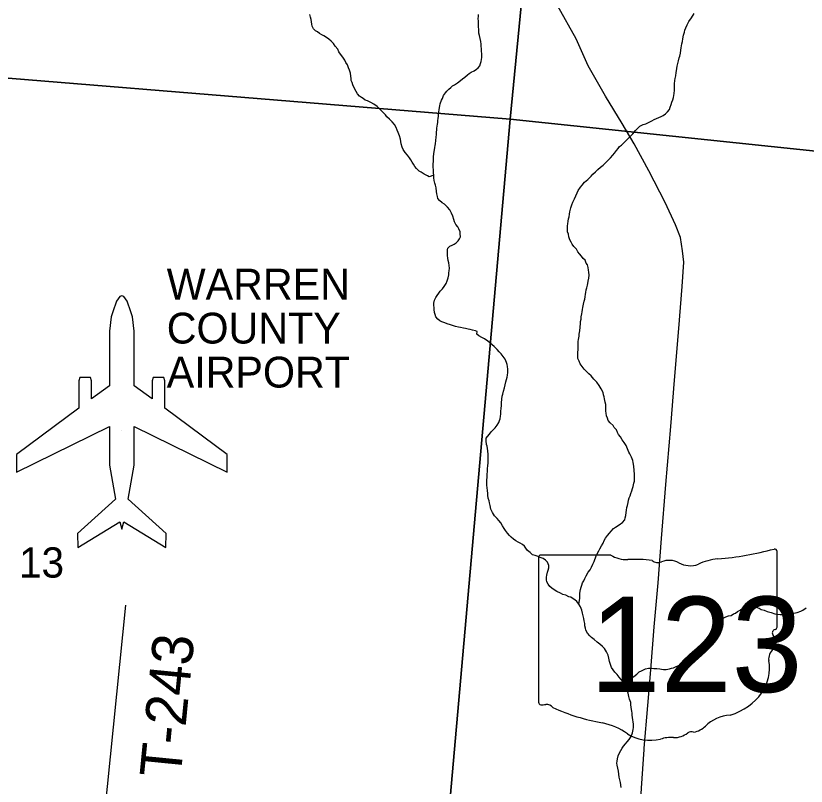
# Model space of a CAD drawing. Extents: x 1310247 to 1664935, y 284496 to 704931.
# Drawn here: x 1473230 to 1478998, y 534778 to 540403 of the extents above; entities that cross this region are included whole.
import ezdxf

# ---------------------------------------------------------------- set-up
doc = ezdxf.new("R2010")
doc.units = 0
for name, color, linetype in [('GM_X_Airport_Class_2', 7, 'Continuous'), ('GM_X_County', 7, 'Continuous'), ('GM_X_County_Subdivision_Text', 7, 'Continuous'), ('GM_X_Interstate_Shield', 7, 'Continuous'), ('GM_X_Major_River', 7, 'Continuous'), ('GM_X_Minor_River_Text', 7, 'Continuous'), ('GM_X_Rail_Line_Text', 7, 'Continuous'), ('GM_X_Township_Subdivision', 7, 'Continuous'), ('GM_X_Unincorporated', 7, 'Continuous'), ('GM_X_Unincorporated_Location', 7, 'Continuous'), ('GM_X_US_Location', 7, 'Continuous')]:
    doc.layers.add(name, color=color, linetype=linetype)

msp = doc.modelspace()

# ---------------------------------------------------------------- linework, layer by layer
at = {"layer": 'GM_X_Airport_Class_2'}
for p, q in [((1477572.3, 536466.3), (1477062.6, 536466.3)), ((1478785.7, 535939.7), (1478785.7, 536492.5)), ((1477045.5, 536448.1), (1477045.5, 535391.5)), ((1478785.5, 535939.9), (1478785.7, 535939.7))]:
    msp.add_line(p, q, dxfattribs=at)
for centre, major_axis, start_param, end_param in [((1477065.4, 536450.4), (20.2, 0), 1.712693, 3.28349), ((1477693.6, 536589), (195.5, 0), 4.042523, 4.731795), ((1478165.8, 537906.8), (1845.5, 0), 4.814394, 5.042369), ((1478766.4, 536494.8), (19.4, 0), 6.141152, 7.989035), ((1477758.5, 535873.1), (702, 0), 1.404758, 1.657858), ((1477917.8, 536455.8), (56.4, 0), 3.836095, 5.185415), ((1478000.6, 536333.7), (117.3, 0), 0.950623, 2.079405), ((1478152, 536501.2), (141.1, 0), 4.081561, 5.145723), ((1478401.2, 536143.6), (371.3, 0), 1.699011, 2.107814), ((1478765, 535937.6), (20.7, 0), 5.05454, 6.418171), ((1478781.2, 535899.2), (30, 0), 1.883978, 3.671073), ((1478590.5, 535829.3), (180, 0), 5.934695, 6.695948), ((1478855.1, 535708.4), (130.9, 0), 2.387724, 3.262537), ((1478269.2, 535638.1), (461.6, 0), 5.101752, 6.440018), ((1477065.6, 535389.2), (20.3, 0), 3.00124, 4.508301), ((1477068.7, 535497.3), (155.2, 0), 4.665946, 4.897461), ((1477100.4, 535330.5), (56, 0), 0.519207, 1.627899), ((1477807, 536279.9), (1332.7, 0), 4.195997, 4.488961), ((1478463.8, 535094.8), (252.8, 0), 1.647645, 2.488434), ((1477409.7, 534916.8), (417, 0), 0.823519, 1.323587), ((1478143.5, 535289.1), (149.1, 0), 4.937069, 5.64225), ((1477860.7, 535325.3), (264.6, 0), 4.026481, 4.996735), ((1478013.6, 534960), (217.4, 0), 1.495662, 1.94098), ((1478032.9, 535246.1), (141, 0), 4.691044, 5.507374), ((1478160.4, 535143.8), (39.7, 0), 1.147584, 2.315152)]:
    msp.add_ellipse(centre, major_axis=major_axis, ratio=0.8, start_param=start_param, end_param=end_param, dxfattribs=at)
at = {"layer": 'GM_X_County'}
for points in [[(1477436.1, 545815.4), (1476836.6, 539649.6), (1471355, 540097.2), (1471810.7, 544955.4)], [(1482824.4, 544500.5), (1482296.8, 539077.3), (1476836.6, 539649.6), (1477436.1, 545815.4)], [(1476836.6, 539649.6), (1476252.8, 533037.6), (1471180, 533489.6), (1470718.9, 533530.8), (1471355, 540097.2)], [(1482296.8, 539077.3), (1481688, 532623.9), (1476536.2, 533008.3), (1476252.8, 533037.6), (1476836.6, 539649.6)]]:
    msp.add_lwpolyline(points, close=True, dxfattribs=at)
at = {"layer": 'GM_X_County_Subdivision_Text'}
msp.add_lwpolyline([(1473876.8, 534559.8), (1474031.7, 536099.1)], dxfattribs=at)
at = {"layer": 'GM_X_Interstate_Shield'}
for points in [[(1477816, 535045.3), (1477816.7, 535055), (1477842, 535367.3), (1477864.2, 535627.6), (1477889.6, 535941.9), (1477917.2, 536264.2), (1477942.8, 536586.6), (1477974.1, 536981), (1478010.2, 537405.4), (1478038.2, 537741.7), (1478069.1, 538120.1), (1478094.3, 538426.4), (1478104.5, 538604.7), (1478096.4, 538687.1), (1478080.6, 538783.7), (1478044.6, 538876.8), (1477968.1, 539041), (1477848.9, 539270.5), (1477743.1, 539467.5), (1477654.2, 539618), (1477534.3, 539815.3), (1477406.9, 540036.9), (1477318.7, 540235.4), (1477185.9, 540473.5)], [(1478440.3, 532324.5), (1478351.4, 532449.3), (1478259.2, 532585.2), (1478211.2, 532680.6), (1478127.9, 532868.5), (1478068.3, 533037.8), (1478010.5, 533291.2), (1477940, 533541.6), (1477877.4, 533781.8), (1477824.4, 534011.7), (1477801.3, 534140.6), (1477788.6, 534285.3), (1477784.4, 534447.9), (1477783.1, 534562.3), (1477795.8, 534764.6), (1477816, 535045.3)]]:
    msp.add_lwpolyline(points, dxfattribs=at)
at = {"layer": 'GM_X_Major_River'}
msp.add_line((1474003.5, 537376.6), (1474003.5, 537376.6), dxfattribs=at)
at = {"layer": 'GM_X_Minor_River_Text'}
for points in [[(1476280, 539239.5), (1476247.5, 539226.5), (1476233.7, 539234.9), (1476209.9, 539245.7), (1476188.3, 539260.3), (1476172.5, 539268.8), (1476153, 539287.5), (1476141.4, 539301.9), (1476132, 539320.2), (1476122.4, 539334.5), (1476112.9, 539350.8), (1476103.4, 539367.2), (1476088, 539385.7), (1476070.6, 539406.2), (1476057.2, 539426.7), (1476049.7, 539444.9), (1476042.5, 539469.2), (1476039, 539485.3), (1476037.5, 539501.4), (1476030.3, 539525.7), (1476021, 539550), (1476013.6, 539568.3), (1476006.2, 539588.5), (1475992.9, 539609), (1475977.5, 539629.5), (1475956, 539648.2), (1475938.4, 539664.7), (1475926.9, 539679.1), (1475909.5, 539699.7), (1475890, 539718.3), (1475866.6, 539741.1), (1475843.1, 539757.8), (1475821.4, 539770.5), (1475797.6, 539781.3), (1475779.8, 539787.8), (1475766, 539798.3), (1475752.2, 539806.7), (1475738.5, 539817.2), (1475723, 539833.7), (1475704, 539866.3), (1475689, 539898.8), (1475683.5, 539915), (1475678, 539931.2), (1475676.4, 539945.3), (1475675, 539963.3), (1475671.7, 539983.5), (1475664.4, 540005.8), (1475656.9, 540024), (1475649.6, 540046.3), (1475638.1, 540062.7), (1475630.6, 540078.9), (1475617.3, 540101.4), (1475599.9, 540121.9), (1475588.4, 540140.3), (1475579, 540158.6), (1475561.7, 540181.2), (1475548.2, 540199.7), (1475530.7, 540218.2), (1475515.1, 540232.7), (1475497.5, 540245.3), (1475477.7, 540255.9), (1475464, 540264.4), (1475446.1, 540272.9), (1475430.5, 540285.4), (1475416.7, 540293.9), (1475403.1, 540308.3), (1475393.7, 540328.6), (1475390.2, 540342.8), (1475388.7, 540358.8), (1475385.3, 540377), (1475379.8, 540393.2), (1475374.4, 540413.4)], [(1476618.4, 540236.7), (1476615.1, 540258.9), (1476609.7, 540277.1), (1476608.1, 540291.2), (1476608.6, 540305.2), (1476607, 540319.2), (1476607.6, 540335.2), (1476606, 540349.3), (1476606.6, 540367.3), (1476605.1, 540381.4), (1476605.7, 540399.4), (1476606.1, 540413.4)], [(1477985.1, 539701.7), (1477999.8, 539719.3), (1478006.4, 539737.1), (1478013, 539755), (1478017.6, 539772.9), (1478026.3, 539790.6), (1478030.8, 539806.5), (1478033.3, 539820.4), (1478033.8, 539836.5), (1478036.6, 539860.4), (1478037.4, 539886.4), (1478038.1, 539906.4), (1478040.9, 539930.4), (1478041.4, 539944.4), (1478046, 539964.3), (1478048.8, 539988.3), (1478051.3, 540002.2), (1478053.9, 540018.2), (1478056.5, 540036.1), (1478061.1, 540054), (1478065.7, 540073.9), (1478072.5, 540095.7), (1478077, 540109.6), (1478081.7, 540131.5), (1478084.4, 540153.4), (1478087, 540169.4), (1478089.4, 540183.3), (1478091.9, 540197.3), (1478094.5, 540215.2), (1478097.2, 540235.2), (1478102.1, 540261.1), (1478110.9, 540284.8), (1478113.4, 540298.8), (1478119.9, 540314.6), (1478130.7, 540336.3), (1478141.6, 540362), (1478160.6, 540389.5), (1478181.6, 540418.9)], [(1476394.3, 538560.8), (1476392.9, 538580.9), (1476389.5, 538599), (1476386.1, 538617.2), (1476382.6, 538633.3), (1476381.2, 538653.4), (1476379.8, 538669.4), (1476380.6, 538693.5), (1476383, 538707.4), (1476397.5, 538721), (1476413.9, 538728.5), (1476430.2, 538736), (1476444.6, 538745.6), (1476459.1, 538759.2), (1476467.6, 538774.9), (1476474.1, 538788.8), (1476472.8, 538810.8), (1476473.3, 538824.8), (1476464, 538847.2), (1476456.5, 538863.4), (1476441, 538879.9), (1476431.5, 538898.2), (1476426.1, 538916.4), (1476418.9, 538940.7), (1476409.5, 538961), (1476396.3, 538987.5), (1476380.8, 539006), (1476357.4, 539026.8), (1476341.7, 539037.2), (1476322.1, 539053.9), (1476310.6, 539070.3), (1476307.1, 539084.4), (1476303.6, 539102.5), (1476300.2, 539120.7), (1476297.1, 539146.8), (1476293.7, 539166.9), (1476288.2, 539181.1), (1476282.8, 539201.3), (1476281.4, 539219.4), (1476280, 539239.5), (1476278.6, 539255.6), (1476277.2, 539275.6), (1476276, 539299.7), (1476274.7, 539319.8), (1476277.4, 539341.8), (1476277.9, 539357.8), (1476278.4, 539371.8), (1476281.2, 539397.7), (1476286.1, 539423.6), (1476288.7, 539441.6), (1476289.2, 539455.6), (1476291.7, 539469.5), (1476294.5, 539493.5), (1476297.3, 539517.4), (1476299.9, 539535.4), (1476300.5, 539555.4), (1476303, 539569.3), (1476303.5, 539583.3), (1476305.9, 539597.3), (1476308.4, 539611.2), (1476308.9, 539625.2), (1476309.3, 539639.3), (1476311.8, 539653.2), (1476314.4, 539671.2), (1476314.9, 539687.2), (1476317.5, 539703.1), (1476319.9, 539717.1), (1476322.5, 539733), (1476324.9, 539747), (1476327.4, 539760.9), (1476336.3, 539786.7), (1476342.8, 539800.5), (1476351.5, 539820.3), (1476366.2, 539839.8), (1476376.7, 539853.5), (1476391.2, 539867.1), (1476403.7, 539880.8), (1476418.1, 539892.3), (1476432.5, 539899.9), (1476453, 539913.3), (1476475.7, 539930.6), (1476490.1, 539942.2), (1476506.6, 539955.7), (1476525.2, 539971.2), (1476539.7, 539982.8), (1476554.1, 539992.3), (1476574.5, 540001.7), (1476590.9, 540013.2), (1476605.3, 540022.8), (1476615.9, 540038.5), (1476622.4, 540054.3), (1476627, 540070.2), (1476627.4, 540084.2), (1476629.9, 540098.2), (1476630.7, 540122.2), (1476629.5, 540148.3), (1476628.1, 540164.3), (1476626.5, 540178.4), (1476625.1, 540196.5), (1476623.7, 540214.5), (1476618.4, 540236.7)], [(1477333, 537962.9), (1477333.6, 537982.9), (1477334.4, 538004.9), (1477335, 538024.9), (1477337.5, 538038.9), (1477340.3, 538064.8), (1477340.8, 538078.8), (1477345.6, 538102.7), (1477348.5, 538130.7), (1477351.4, 538156.6), (1477351.9, 538170.7), (1477356.5, 538188.5), (1477357.1, 538206.5), (1477359.8, 538226.5), (1477362.3, 538242.4), (1477364.8, 538258.4), (1477367.4, 538274.3), (1477372.2, 538298.2), (1477378.9, 538320.1), (1477383.4, 538334), (1477386, 538351.9), (1477388.6, 538369.8), (1477391.1, 538383.8), (1477393.7, 538401.8), (1477396.2, 538417.7), (1477402.8, 538435.5), (1477405.3, 538449.5), (1477407.8, 538465.4), (1477412.6, 538487.3), (1477413.3, 538509.3), (1477412, 538531.4), (1477410.5, 538545.5), (1477407.1, 538565.6), (1477401.7, 538583.8), (1477392.1, 538598.1), (1477384.7, 538618.4), (1477371.1, 538630.8), (1477359.6, 538647.2), (1477344.1, 538665.7), (1477332.5, 538680.1), (1477321.1, 538698.5), (1477303.7, 538719.1), (1477290.2, 538735.5), (1477282.6, 538749.8), (1477273.2, 538768.1), (1477265.8, 538788.3), (1477262.4, 538808.5), (1477256.9, 538824.7), (1477255.5, 538842.8), (1477256.4, 538870.8), (1477258.9, 538884.7), (1477261.6, 538904.7), (1477264.1, 538920.6), (1477268.7, 538936.5), (1477271.3, 538954.5), (1477273.9, 538972.4), (1477280.8, 539000.3), (1477287.6, 539022.1), (1477296.3, 539041.8), (1477307.2, 539067.6), (1477315.9, 539089.3), (1477326.7, 539111), (1477335.3, 539128.8), (1477350.1, 539152.4), (1477362.6, 539166), (1477379.4, 539187.5), (1477404.2, 539206.8), (1477429.1, 539232.1), (1477441.6, 539245.7), (1477460.3, 539263.2), (1477476.9, 539280.7), (1477497.6, 539298.1), (1477516.2, 539313.5), (1477534.8, 539329), (1477551.4, 539346.5), (1477570.2, 539366), (1477586.9, 539385.5), (1477599.5, 539401.1), (1477614.1, 539418.7), (1477626.7, 539434.3), (1477635.2, 539448.1), (1477649.6, 539459.7), (1477670.4, 539479.1), (1477695.2, 539502.3), (1477718.1, 539525.7), (1477732.7, 539541.2), (1477751.6, 539564.7), (1477766.1, 539580.3), (1477784.8, 539597.7), (1477809.3, 539609), (1477827.5, 539614.4), (1477841.8, 539622), (1477858.2, 539629.5), (1477872.5, 539637.1), (1477888.9, 539646.6), (1477905.2, 539654.1), (1477923.5, 539661.6), (1477939.8, 539667.1), (1477954.1, 539674.6), (1477972.6, 539688.1), (1477985.1, 539701.7)], [(1476672.2, 536935.5), (1476670.9, 536959.5), (1476667.4, 536973.7), (1476668, 536991.7), (1476668.6, 537011.7), (1476669.4, 537033.7), (1476670.1, 537055.7), (1476672.8, 537075.7), (1476673.5, 537097.7), (1476674.1, 537117.7), (1476676.9, 537139.7), (1476677.6, 537161.7), (1476676.4, 537185.8), (1476676.9, 537199.8), (1476673.7, 537225.9), (1476672.3, 537244), (1476668.8, 537260.1), (1476665.3, 537274.3), (1476662.1, 537300.4), (1476662.7, 537318.4), (1476671.2, 537332.2), (1476685.8, 537349.8), (1476698.4, 537365.4), (1476713, 537381), (1476727.5, 537394.6), (1476742.2, 537414.1), (1476754.9, 537433.8), (1476759.4, 537447.7), (1476763.9, 537461.6), (1476766.5, 537479.5), (1476769, 537495.5), (1476769.6, 537513.5), (1476772.5, 537539.4), (1476775, 537555.4), (1476773.7, 537577.4), (1476776.6, 537603.4), (1476779.3, 537625.4), (1476783.8, 537641.2), (1476788.6, 537663.1), (1476795.4, 537687), (1476802.2, 537708.8), (1476806.9, 537730.7), (1476811.5, 537748.6), (1476816.1, 537764.5), (1476818.6, 537780.4), (1476821.2, 537798.4), (1476820, 537824.4), (1476818.6, 537842.5), (1476817.1, 537856.6), (1476811.6, 537872.8), (1476800.3, 537897.2), (1476786.9, 537915.6), (1476771.4, 537934.1), (1476757.8, 537948.6), (1476742.4, 537967.1), (1476721, 537987.8), (1476707.3, 538000.2), (1476689.7, 538014.8), (1476676, 538027.2), (1476650.5, 538044), (1476630.7, 538054.7), (1476609, 538065.4), (1476595.4, 538079.8), (1476598, 538097.8), (1476584.1, 538102.2), (1476562.1, 538106.9), (1476546.3, 538113.4), (1476532.3, 538115.8), (1476512.3, 538120.4), (1476498.4, 538122.9), (1476474.4, 538127.6), (1476460.4, 538130.1), (1476438.5, 538134.7), (1476424.5, 538139.2), (1476402.7, 538147.8), (1476378.8, 538154.6), (1476361, 538161.2), (1476339.2, 538169.8), (1476325.3, 538176.3), (1476309.7, 538188.8), (1476296.1, 538205.2), (1476290.6, 538221.4), (1476285.1, 538237.6), (1476283.8, 538257.7), (1476282.2, 538271.8), (1476280.8, 538289.9), (1476281.4, 538305.9), (1476286, 538325.8), (1476294.7, 538345.5), (1476305.3, 538361.2), (1476317.9, 538378.9), (1476326.4, 538392.6), (1476343.1, 538410.1), (1476355.7, 538427.8), (1476370.5, 538449.4), (1476377.1, 538467.2), (1476385.9, 538491), (1476390.6, 538510.8), (1476391.1, 538526.9), (1476393.6, 538540.8), (1476394.3, 538560.8)], [(1477338, 536107.5), (1477345.5, 536149.3), (1477346.1, 536167.4), (1477346.6, 536185.4), (1477349.2, 536201.3), (1477351.7, 536215.3), (1477356.2, 536231.2), (1477360.7, 536247), (1477365.3, 536262.9), (1477375.8, 536278.6), (1477382.4, 536294.5), (1477393.1, 536314.2), (1477408.1, 536341.8), (1477420.6, 536357.4), (1477431.3, 536377.1), (1477440.1, 536398.9), (1477450.8, 536418.6), (1477455.3, 536432.4), (1477461.7, 536446.3), (1477466.2, 536460.2), (1477472.7, 536474), (1477485.5, 536497.6), (1477492, 536511.5), (1477504.8, 536533.1), (1477515.5, 536552.8), (1477524.2, 536572.6), (1477534.7, 536588.3), (1477547.5, 536607.9), (1477562.1, 536625.5), (1477574.7, 536641.2), (1477591.3, 536658.7), (1477607.8, 536670.2), (1477626.2, 536681.6), (1477642.8, 536695.1), (1477657.1, 536704.7), (1477673.8, 536722.2), (1477678.3, 536738.1), (1477680.9, 536754.1), (1477683.6, 536776), (1477686.2, 536794), (1477688.9, 536813.9), (1477693.4, 536827.8), (1477698.1, 536849.7), (1477702.7, 536867.6), (1477707.2, 536883.5), (1477713.8, 536899.3), (1477718.3, 536915.2), (1477727, 536935), (1477731.6, 536950.8), (1477736.1, 536966.7), (1477740.9, 536990.6), (1477745.5, 537006.5), (1477745.9, 537020.5), (1477744.6, 537042.6), (1477745.1, 537056.6), (1477744, 537082.7), (1477741, 537114.8), (1477735.8, 537141), (1477732.3, 537157.2), (1477723, 537179.5), (1477711.8, 537203.9), (1477704.2, 537218.2), (1477694.9, 537240.5), (1477683.7, 537264.9), (1477670.3, 537287.3), (1477654.9, 537307.8), (1477643.6, 537328.2), (1477628.1, 537346.7), (1477620.5, 537361), (1477613.2, 537381.2), (1477597.6, 537397.8), (1477590.1, 537412), (1477568.6, 537430.7), (1477553.1, 537449.2), (1477547.6, 537465.4), (1477542.1, 537481.6), (1477538.8, 537501.7), (1477537.2, 537515.8), (1477535.9, 537537.9), (1477534.9, 537566), (1477531.4, 537582.1), (1477526.1, 537606.3), (1477522.7, 537622.4), (1477519.1, 537636.6), (1477515.6, 537652.7), (1477502.4, 537679.2), (1477487.2, 537703.7), (1477469.9, 537728.3), (1477448.5, 537751), (1477429.2, 537773.6), (1477411.7, 537790.2), (1477396.1, 537806.7), (1477378.6, 537823.2), (1477363.2, 537843.8), (1477349.7, 537862.2), (1477340.4, 537882.5), (1477332.9, 537900.8), (1477331.5, 537916.8), (1477332, 537932.9), (1477332.5, 537948.9), (1477333, 537962.9)], [(1477734.2, 535263.8), (1477730.7, 535279.9), (1477729.2, 535296), (1477727.7, 535312.1), (1477726.2, 535326.1), (1477721, 535352.3), (1477719.7, 535374.4), (1477718.2, 535388.5), (1477709, 535412.8), (1477703.6, 535433), (1477698.4, 535457.2), (1477689.1, 535481.5), (1477681.6, 535495.8), (1477676.1, 535514), (1477662.9, 535540.5), (1477645.5, 535561), (1477634, 535575.4), (1477618.5, 535593.9), (1477601, 535610.5), (1477589.4, 535626.9), (1477578, 535645.3), (1477568.9, 535673.6), (1477563.4, 535689.8), (1477558.2, 535714), (1477552.8, 535734.2), (1477541.5, 535758.6), (1477526.3, 535783.1), (1477510.7, 535797.6), (1477491.2, 535816.3), (1477473.6, 535830.8), (1477450.1, 535849.6), (1477432.5, 535864.2), (1477418.8, 535876.6), (1477403.4, 535895.1), (1477390, 535917.5), (1477388.5, 535931.6), (1477383.1, 535949.8), (1477381.6, 535965.9), (1477378.2, 535986), (1477374.8, 536002.2), (1477371.4, 536022.3), (1477366, 536042.5), (1477360.8, 536064.7), (1477351.4, 536087), (1477338, 536107.5), (1477324.7, 536127.9), (1477310.9, 536138.4), (1477297.1, 536146.8), (1477279.5, 536159.4), (1477265.5, 536161.8), (1477243.7, 536172.5), (1477221.9, 536179.2), (1477204.1, 536187.8), (1477178.4, 536200.6), (1477158.6, 536211.2), (1477140.9, 536223.8), (1477127.3, 536236.2), (1477115.8, 536252.6), (1477106.3, 536270.9), (1477102.8, 536285.1), (1477103.5, 536305.1), (1477105.9, 536319), (1477110.7, 536340.9), (1477115.2, 536356.8), (1477119.7, 536372.7), (1477120.3, 536390.7), (1477111, 536413), (1477095.4, 536427.5), (1477077.8, 536440.1), (1477055.9, 536448.8), (1477042.1, 536455.2), (1477020.2, 536461.9), (1477000.3, 536468.5), (1476982.8, 536485.1), (1476965.2, 536499.7), (1476951.7, 536516.1), (1476942.1, 536530.4), (1476928.4, 536542.9), (1476910.7, 536553.4), (1476896.9, 536559.9), (1476879.1, 536570.5), (1476861.5, 536583), (1476845.9, 536597.5), (1476832.2, 536610), (1476818.7, 536626.4), (1476803.2, 536644.9), (1476793.6, 536659.2), (1476782.3, 536679.6), (1476768.9, 536702.1), (1476755.4, 536718.5), (1476741.8, 536733), (1476724.4, 536753.5), (1476709.1, 536776), (1476697.8, 536800.4), (1476692.7, 536828.7), (1476687.3, 536846.8), (1476683.8, 536861), (1476678.4, 536881.2), (1476675.1, 536903.3), (1476673.6, 536917.4), (1476672.2, 536935.5)], [(1477662.9, 535540.5), (1477715.7, 535554.9), (1477740.5, 535578.2), (1477763.3, 535597.5), (1477779.9, 535613), (1477796.2, 535620.5), (1477810.5, 535628.1), (1477826.8, 535635.6), (1477847, 535639), (1477869.2, 535640.3), (1477887.2, 535637.7), (1477907.2, 535637.1), (1477929.3, 535634.4), (1477943.2, 535632), (1477957.2, 535629.6), (1477977.4, 535630.9), (1477999.6, 535634.3), (1478015.8, 535639.8), (1478030, 535643.3), (1478048.4, 535652.8), (1478062.7, 535658.4), (1478081.1, 535667.8), (1478097.4, 535677.3), (1478119.9, 535688.7), (1478134.3, 535698.2), (1478150.7, 535707.7), (1478167.1, 535719.2), (1478183.7, 535732.8), (1478198.1, 535744.3), (1478216.6, 535755.8), (1478233.1, 535769.3), (1478249.7, 535784.8), (1478264.1, 535796.4), (1478282.8, 535813.9), (1478299.6, 535835.4), (1478308.2, 535853.1), (1478314.8, 535871), (1478317.5, 535890.9), (1478320, 535906.9), (1478322.5, 535920.8), (1478325, 535936.8), (1478335.6, 535952.5), (1478346.1, 535968.2), (1478362.7, 535981.7), (1478377.1, 535993.3), (1478391.6, 536004.8), (1478412, 536014.2), (1478432.3, 536021.6), (1478450.5, 536025.1), (1478467, 536036.6), (1478483.2, 536042.1), (1478497.7, 536053.7), (1478516.1, 536063.1), (1478530.6, 536076.7), (1478551, 536088.1), (1478565.2, 536091.6), (1478581.3, 536093.2), (1478601.4, 536092.5), (1478621.4, 536087.9), (1478637.3, 536083.4), (1478655.2, 536078.8), (1478670.9, 536068.3), (1478692.9, 536063.7), (1478714.7, 536055), (1478742.5, 536046.1), (1478768.4, 536037.3), (1478788.4, 536034.7), (1478808.4, 536032), (1478830.5, 536031.4), (1478846.5, 536030.9), (1478868.7, 536034.2), (1478888.9, 536035.6), (1478909.2, 536040.9), (1478933.4, 536046.2), (1478959.9, 536057.4), (1478974.2, 536063), (1478998.9, 536080.2)], [(1477647.6, 534769.5), (1477642.7, 534805.8), (1477637.3, 534824), (1477634, 534844.1), (1477630.7, 534866.2), (1477627.4, 534888.4), (1477624.1, 534910.5), (1477618.8, 534932.7), (1477617.2, 534946.8), (1477617.7, 534960.8), (1477620.3, 534978.8), (1477627.1, 535000.6), (1477635.8, 535022.4), (1477644.4, 535040.1), (1477655, 535055.8), (1477665.5, 535069.5), (1477680.1, 535087.1), (1477692.7, 535102.8), (1477707.4, 535120.3), (1477720.1, 535142), (1477731, 535167.7), (1477735.9, 535193.6), (1477738.4, 535207.5), (1477737.1, 535231.6), (1477735.7, 535247.7), (1477734.2, 535263.8)]]:
    msp.add_lwpolyline(points, dxfattribs=at)
at = {"layer": 'GM_X_Unincorporated'}
msp.add_lwpolyline([(1473690.7, 537537.4), (1473234.3, 537199.9), (1473234.3, 537070.4), (1473913.3, 537405), (1473913.3, 537123.2), (1473958.3, 536873.8), (1473678.9, 536623.2), (1473683.3, 536520), (1473989.4, 536709.7), (1474003.5, 536654.2), (1474017.6, 536709.7), (1474323.6, 536520), (1474328, 536623.2), (1474048.6, 536873.8), (1474093.7, 537123.2), (1474093.7, 537405), (1474772.7, 537070.4), (1474772.7, 537199.9), (1474316.3, 537537.4), (1474316.3, 537738.9), (1474309.2, 537763.4), (1474231.5, 537763.4), (1474224.4, 537738.9), (1474224.4, 537605.4), (1474093.7, 537702), (1474093.7, 537702), (1474093.7, 538099.9), (1474080.5, 538205.1), (1474069.6, 538242.6), (1474042.6, 538319.2), (1474017.7, 538353.2), (1474003.5, 538359.2), (1473989.3, 538353.2), (1473964.3, 538319.2), (1473937.4, 538242.6), (1473926.4, 538205.1), (1473913.3, 538099.9), (1473913.3, 537702), (1473782.5, 537605.4), (1473782.5, 537738.9), (1473775.5, 537763.4), (1473697.7, 537763.4), (1473690.7, 537738.9)], close=True, dxfattribs=at)

# ---------------------------------------------------------------- texts
at = {"layer": 'GM_X_Airport_Class_2'}
msp.add_text('123', height=696.1, dxfattribs=at).set_placement((1477418.7, 535466))
at = {"layer": 'GM_X_Rail_Line_Text'}
for s, p in [('WARREN', (1474331, 538331.6)), ('COUNTY', (1474331, 538010.4)), ('AIRPORT', (1474331, 537689.2))]:
    msp.add_text(s, height=225, rotation=0.00001, dxfattribs=at).set_placement(p)
at = {"layer": 'GM_X_Township_Subdivision'}
msp.add_text('T-243', height=300, rotation=84.3732, dxfattribs=at).set_placement((1474431.2, 534831))
at = {"layer": 'GM_X_Unincorporated_Location'}
for s in ['s', 'r']:
    msp.add_text(s, height=1, dxfattribs=at).set_placement((1477896, 535849.6))
msp.add_text('123', height=1, rotation=0.00001, dxfattribs=at).set_placement((1477543, 535776.8))
at = {"layer": 'GM_X_US_Location'}
msp.add_text('13', height=221, rotation=0.00001, dxfattribs=at).set_placement((1473253, 536301.4))

doc.saveas('drawing.dxf')
